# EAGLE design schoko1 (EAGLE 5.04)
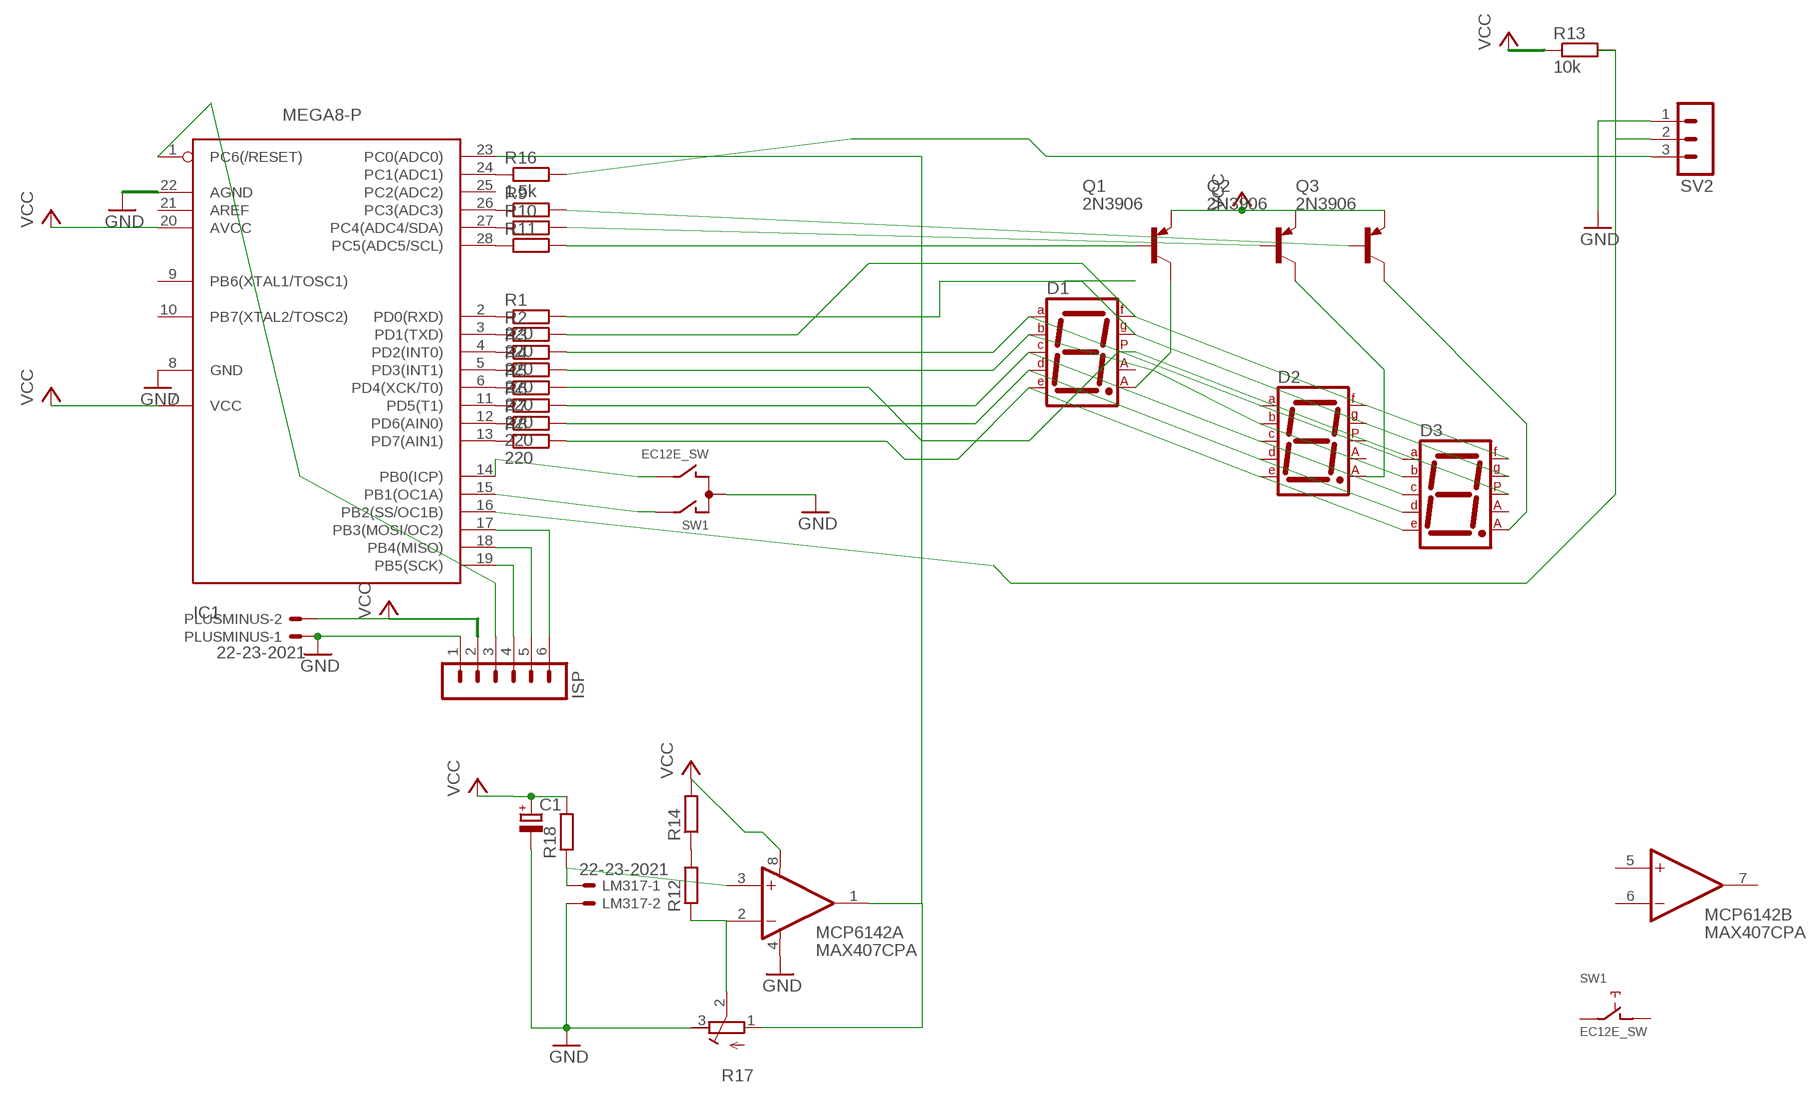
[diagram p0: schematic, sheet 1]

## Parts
C1  CPOL-EUTT2D5L  [TT2D5L]
D1  7SEG-CA  [7SEG-13]
D2  7SEG-CA  [7SEG-13]
D3  7SEG-CA  [7SEG-13]
IC1  MEGA8-P  [DIL28-3]
ISP  MA06-1  [MA06-1]
LM317  22-23-2021  [22-23-2021]
MCP6142  MAX407CPA  [DIL08]
PLUSMINUS  22-23-2021  [22-23-2021]
Q1  2N3906  [TO92]
Q2  2N3906  [TO92]
Q3  2N3906  [TO92]
R1  220  R-EU_0204/7  [0204/7]
R2  220  R-EU_0204/7  [0204/7]
R3  220  R-EU_0204/7  [0204/7]
R4  220  R-EU_0204/7  [0204/7]
R5  220  R-EU_0204/7  [0204/7]
R6  220  R-EU_0204/7  [0204/7]
R7  220  R-EU_0204/7  [0204/7]
R8  220  R-EU_0204/7  [0204/7]
R9  R-EU_0204/7  [0204/7]
R10  R-EU_0204/7  [0204/7]
R11  R-EU_0204/7  [0204/7]
R12  R-EU_0204/7  [0204/7]
R13  10k  R-EU_0204/7  [0204/7]
R14  R-EU_0204/7  [0204/7]
R16  1.5k  R-EU_0204/7  [0204/7]
R17  R-TRIMM64P  [RTRIM64P]
R18  R-EU_0204/7  [0204/7]
SV2  MA03-1  [MA03-1]
SW1  EC12E_SW  [ALPS_EC12E_SW]

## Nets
GND: C1.- IC1.8(GND) IC1.22(AGND) ISP.1 LM317.2 MCP6142.4(A:V-) PLUSMINUS.1 R17.3(A) SV2.1 SW1.C
N$1: D1.7(A) D2.7(A) D3.7(A) R3.2
N$2: D1.6(B) D2.6(B) D3.6(B) R4.2
N$3: D1.4(C) D2.4(C) D3.4(C) R6.2
N$4: D1.2(D) D2.2(D) D3.2(D) R7.2
N$5: D1.1(E) D2.1(E) D3.1(E) R8.2
N$6: D1.9(F) D2.9(F) D3.9(F) R2.2
N$7: D1.8(CA2) Q1.1(C)
N$8: IC1.4(PD2(INT0)) R3.1
N$9: IC1.5(PD3(INT1)) R4.1
N$10: IC1.6(PD4(XCK/T0)) R5.1
N$11: IC1.11(PD5(T1)) R6.1
N$12: IC1.12(PD6(AIN0)) R7.1
N$13: IC1.13(PD7(AIN1)) R8.1
N$14: IC1.2(PD0(RXD)) R1.1
N$15: IC1.3(PD1(TXD)) R2.1
N$16: D2.8(CA2) Q2.1(C)
N$17: D1.5(DP) D2.5(DP) D3.5(DP) R5.2
N$18: D1.10(G) D2.10(G) D3.10(G) R1.2
N$20: D3.8(CA2) Q3.1(C)
N$21: IC1.28(PC5(ADC5/SCL)) R11.1
N$22: IC1.27(PC4(ADC4/SDA)) R10.1
N$23: IC1.26(PC3(ADC3)) R9.1
N$24: Q3.2(B) R9.2
N$25: Q2.2(B) R10.2
N$26: Q1.2(B) R11.2
N$27: IC1.16(PB2(SS/OC1B)) R13.2 SV2.2
N$28: IC1.1(PC6(/RESET)) ISP.3
N$29: IC1.19(PB5(SCK)) ISP.4
N$30: IC1.18(PB4(MISO)) ISP.5
N$31: IC1.17(PB3(MOSI/OC2)) ISP.6
N$33: IC1.14(PB0(ICP)) SW1.B
N$34: IC1.15(PB1(OC1A)) SW1.A
N$37: IC1.24(PC1(ADC1)) R16.1
N$39: R12.2 R14.1
N$43: R16.2 SV2.3
N$44: IC1.23(PC0(ADC0)) MCP6142.1(A:OUT) R17.1(E)
N$45: MCP6142.2(A:-IN) R12.1 R17.2(S)
N$47: LM317.1 MCP6142.3(A:+IN) R18.1
VCC: C1.+ IC1.7(VCC) IC1.20(AVCC) ISP.2 MCP6142.8(A:V+) PLUSMINUS.2 Q1.3(E) Q2.3(E) Q3.3(E) R13.1 R14.2 R18.2
Unconnected: D1.3(CA1) D2.3(CA1) D3.3(CA1) IC1.9(PB6(XTAL1/TOSC1)) IC1.10(PB7(XTAL2/TOSC2)) IC1.21(AREF) IC1.25(PC2(ADC2)) MCP6142.5(B:+IN) MCP6142.6(B:-IN) MCP6142.7(B:OUT) SW1.D SW1.E SW1.GND1(G) SW1.GND2(G)

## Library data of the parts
C1 = resistor:CPOL-EU: POLARIZED CAPACITOR, European symbol
D1-D3 = special:7SEG-CA: 7-segment DISPLAY single anode, 13 mm
IC1 = atmel:MEGA8-P: MICROCONTROLLER 8 Kbytes FLASH, 1 kbytes SRAM, 512 bytes EEPROM, USART, 4-channel 10 bit ADC, 2-channel 8 bit ADC Pin compatible with Atmega48, ATMega88, ATMega168 Source: avr.lbr
ISP = con-lstb:MA06-1: PIN HEADER
LM317 PLUSMINUS = con-molex:22-23-2021: .100" (2.54mm) Center Header - 2 Pin
MCP6142 = maxim:MAX407CPA: OP AMP
Q1-Q3 = transistor-pnp:2N3906: PNP Transistor
R1-R14 R16 R18 = resistor:R-EU_: RESISTOR, European symbol
R17 = resistor:R-TRIMM: Trimm resistor
SV2 = con-lstb:MA03-1: PIN HEADER
SW1 = switch-alps:EC12E_SW: ALPS rotary Encoder EC12E series with switch

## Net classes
0 default: width 0.508 mm, clearance 0.254 mm
1 220: width 0.762 mm, clearance 0.762 mm

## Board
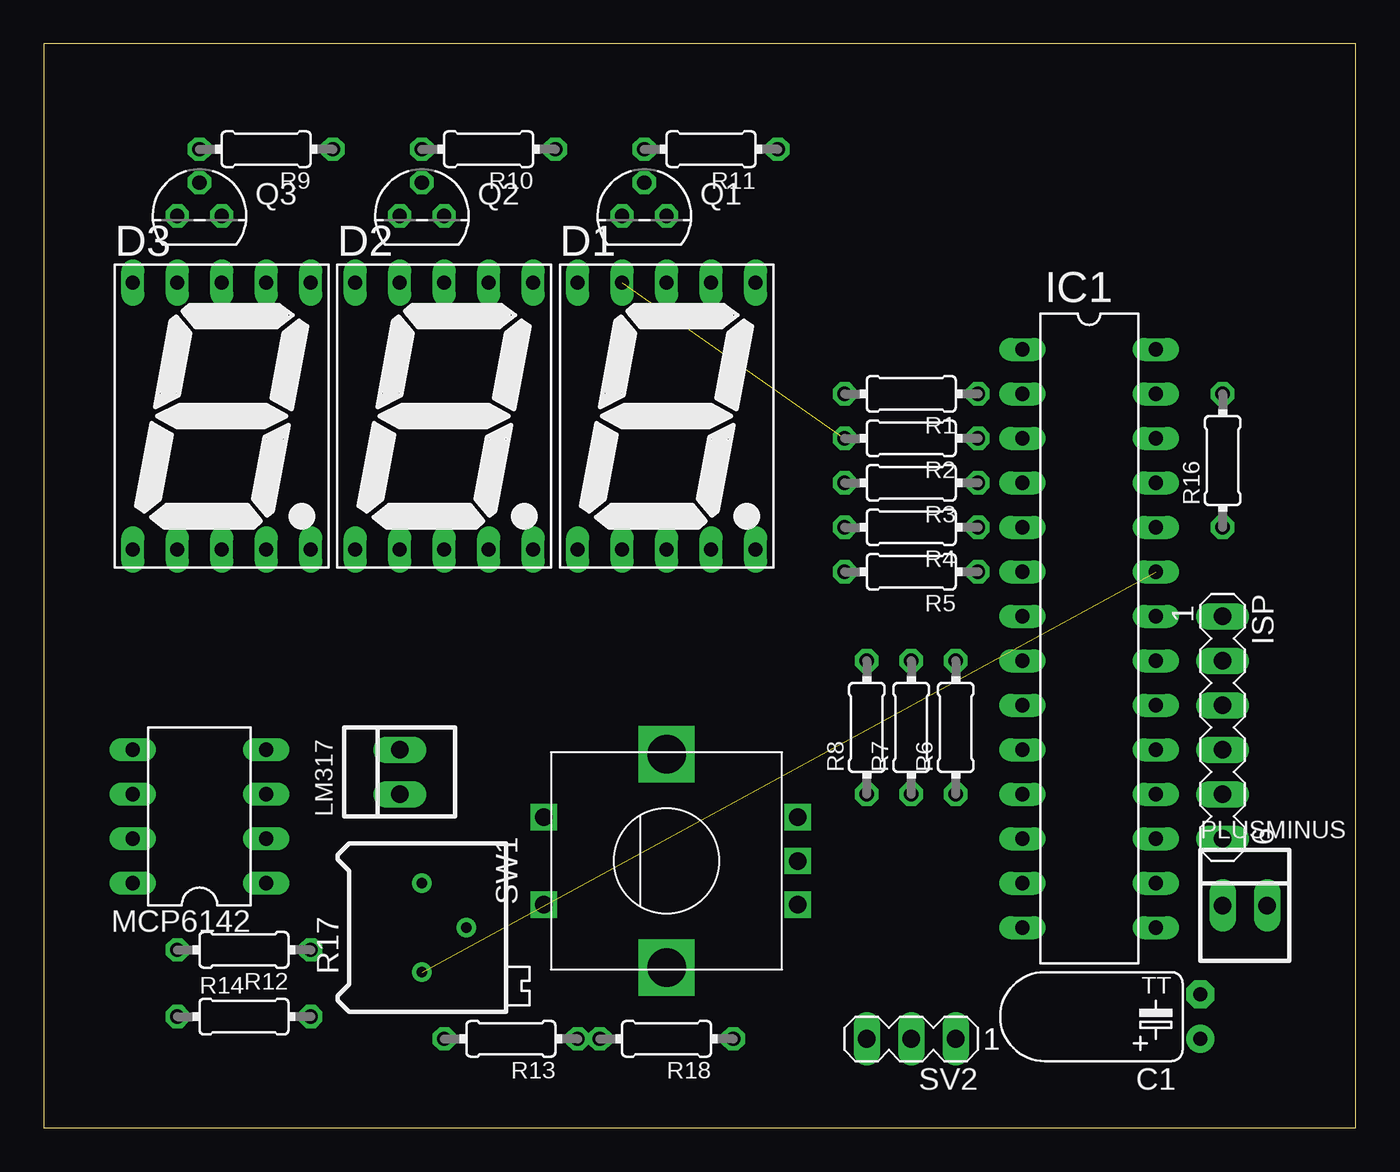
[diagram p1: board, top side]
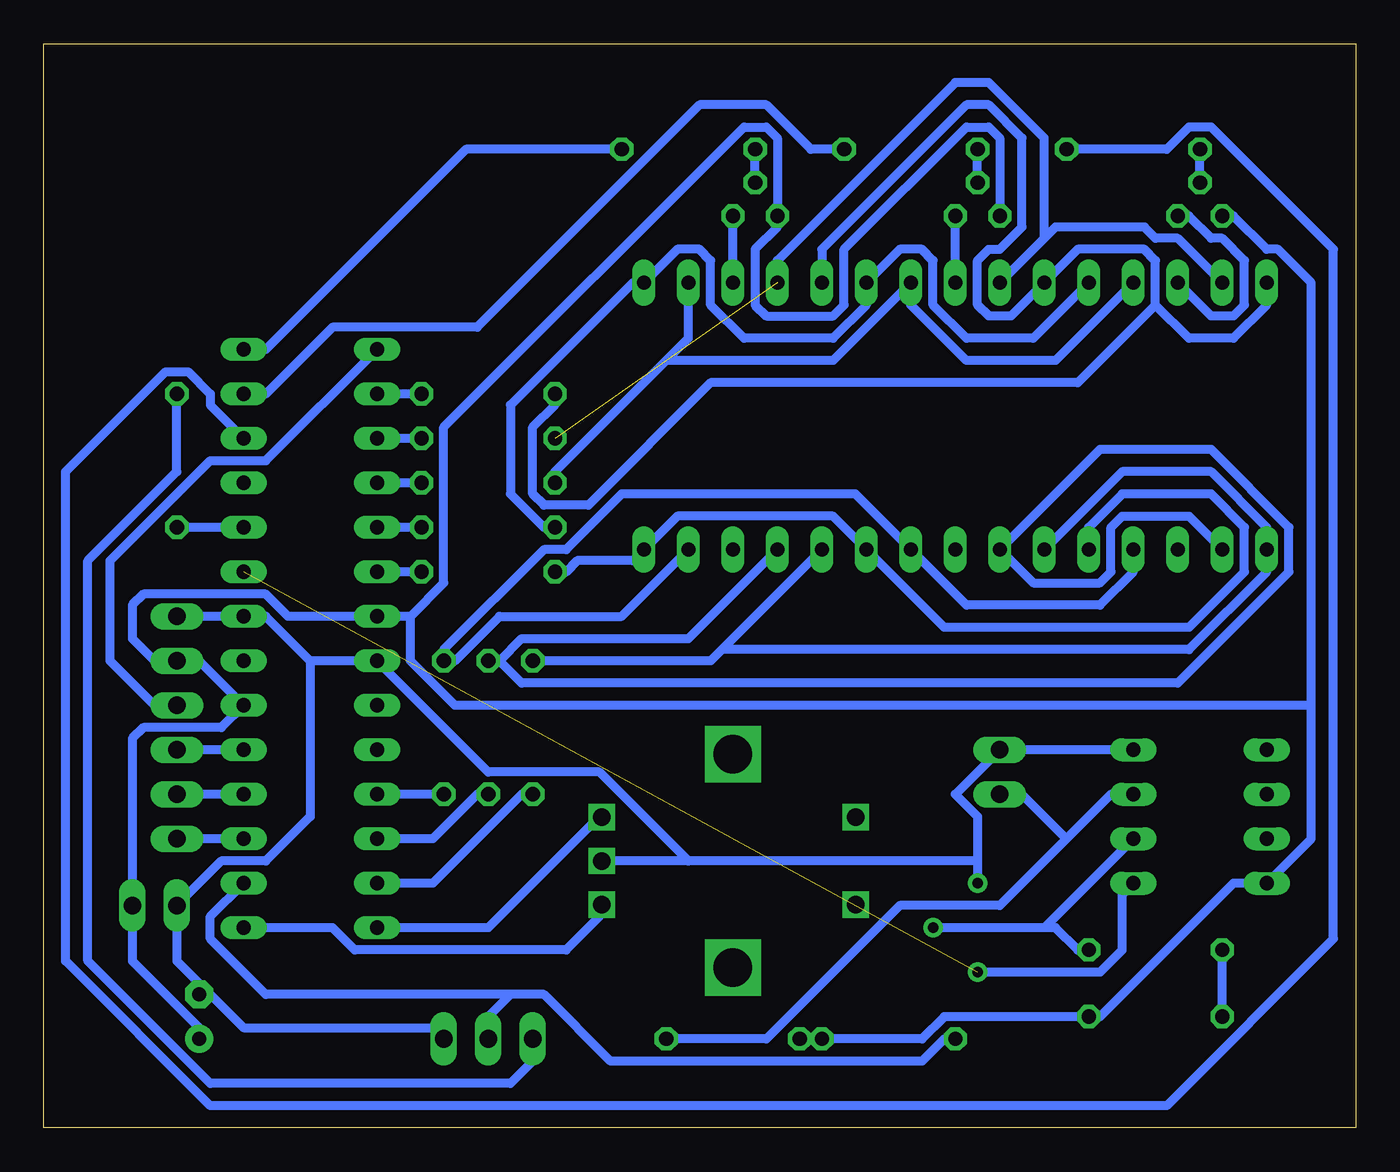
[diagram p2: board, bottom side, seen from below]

Size 74.91 x 61.9 mm. Coordinates in mm from the lower left corner, seen from the top.
Outline: 0,0 74.91,0 74.91,61.9 0,61.9 0,0
Copper layers (1*16): Top 0.035mm / dielectric 1.5mm / Bottom 0.035mm
Design rules "default": minimum track width 10mil, minimum drill 24mil, track to track 8mil, track to pad 8mil, pad to pad 8mil, via to via 8mil, smd to smd 8mil, copper to edge 40mil, drill to drill 8mil, minimum pad ring 10mil, minimum via ring 8mil, stop-mask expansion 4mil, vias tented up to drill 0mil, thermal gap 10mil

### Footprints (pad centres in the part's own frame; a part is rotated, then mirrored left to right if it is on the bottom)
TT2D5L = drill 0.813 pad 1.6 round: + -1.27,0 | drill 0.813 pad 1.6 octagon: - 1.27,0
7SEG-13 = drill 0.813 long: 1 -5.08,-7.62; 2 -2.54,-7.62; 3 0,-7.62; 4 2.54,-7.62; 5 5.08,-7.62; 6 5.08,7.62; 7 2.54,7.62; 8 0,7.62; 9 -2.54,7.62; 10 -5.08,7.62
DIL28-3 = drill 0.813 long: 1 -16.51,-3.81; 2 -13.97,-3.81; 3 -11.43,-3.81; 4 -8.89,-3.81; 5 -6.35,-3.81; 6 -3.81,-3.81; 7 -1.27,-3.81; 8 1.27,-3.81; 9 3.81,-3.81; 10 6.35,-3.81; 11 8.89,-3.81; 12 11.43,-3.81; 13 13.97,-3.81; 14 16.51,-3.81; 15 16.51,3.81; 16 13.97,3.81; 17 11.43,3.81; 18 8.89,3.81; 19 6.35,3.81; 20 3.81,3.81; 21 1.27,3.81; 22 -1.27,3.81; 23 -3.81,3.81; 24 -6.35,3.81; 25 -8.89,3.81; 26 -11.43,3.81; 27 -13.97,3.81; 28 -16.51,3.81
MA06-1 = drill 1.016 long: 1 -6.35,0; 2 -3.81,0; 3 -1.27,0; 4 1.27,0; 5 3.81,0; 6 6.35,0
22-23-2021 = drill 1 long: 1 -1.27,0; 2 1.27,0
DIL08 = drill 0.813 long: 1 -3.81,-3.81; 2 -1.27,-3.81; 3 1.27,-3.81; 4 3.81,-3.81; 5 3.81,3.81; 6 1.27,3.81; 7 -1.27,3.81; 8 -3.81,3.81
TO92 = drill 0.813 octagon: 1 1.27,0; 2 0,1.905; 3 -1.27,0
0204/7 = drill 0.813 octagon: 1 -3.81,0; 2 3.81,0
RTRIM64P = drill 0.61 round: 1 0,-2.54; 2 2.54,0; 3 0,2.54
MA03-1 = drill 1.016 long: 1 -2.54,0; 2 0,0; 3 2.54,0
ALPS_EC12E_SW = drill 1 square: A -2.5,-7.5; B 2.5,-7.5; C 0,-7.5; D -2.5,7; E 2.5,7 | drill 2.2 square: GND1 -6.1,0; GND2 6.1,0

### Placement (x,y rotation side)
C1  66.04,6.35 90 top
D1  35.56,40.64 0 top
D2  22.86,40.64 0 top
D3  10.16,40.64 0 top
IC1  59.69,27.94 270 top
ISP  67.31,22.86 270 top
LM317  20.32,20.32 90 top
MCP6142  8.89,17.78 90 top
PLUSMINUS  68.58,12.7 0 top
Q1  34.29,52.07 0 top
Q2  21.59,52.07 0 top
Q3  8.89,52.07 0 top
R1  49.53,41.91 180 top
R2  49.53,39.37 180 top
R3  49.53,36.83 180 top
R4  49.53,34.29 180 top
R5  49.53,31.75 180 top
R6  52.07,22.86 90 top
R7  49.53,22.86 90 top
R8  46.99,22.86 90 top
R9  12.7,55.88 180 top
R10  25.4,55.88 180 top
R11  38.1,55.88 180 top
R12  11.43,10.16 180 top
R13  26.67,5.08 180 top
R14  11.43,6.35 0 top
R16  67.31,38.1 90 top
R17  21.59,11.43 0 top
R18  35.56,5.08 180 top
SV2  49.53,5.08 180 top
SW1  35.56,15.24 90 top

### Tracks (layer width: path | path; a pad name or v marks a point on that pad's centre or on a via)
GND
  Bottom 0.508: SV2.1 52.7,5.71 63.5,5.71 65.41,7.62 C1.- 66.04,8.25 67.31,9.52 PLUSMINUS.1 64.77,15.24 62.23,15.24 59.69,17.78 59.69,26.67 | 59.69,26.67 62.23,29.21 IC1.22 ISP.1 | 59.69,26.67 IC1.8 49.53,20.32 43.18,20.32 38.1,15.24 | 21.59,15.24 21.59,17.78 22.86,19.05 LM317.2 MCP6142.4 | 21.59,15.24 R17.3 | 21.59,15.24 38.1,15.24 | 38.1,15.24 SW1.C
N$1
  Bottom 0.508: D3.7 17.14,43.82 22.23,43.82 25.4,46.99 D2.7 29.84,43.82 39.37,43.82 | 39.37,43.82 38.1,45.09 D1.7 | 39.37,43.82 45.72,37.46 R3.2
N$2
  Bottom 0.508: D3.6 18.41,45.09 22.23,45.09 24.13,46.99 24.13,49.53 24.77,50.16 26.04,50.16 D2.6 27.94,46.99 29.84,45.09 34.92,45.09 36.83,46.99 36.83,49.53 37.47,50.16 38.73,50.16 D1.6 41.27,48.26 48.26,41.27 48.26,36.2 46.35,34.29 R4.2
N$3
  Bottom 0.508: D3.4 12.7,31.75 14.61,29.84 22.23,29.84 D2.4 28.57,36.2 41.91,36.2 45.09,33.02 46.35,33.02 52.07,27.3 R6.2 51.44,26.67 48.9,29.21 41.91,29.21 D1.4
N$4
  Bottom 0.508: D3.2 9.53,34.93 13.34,34.93 13.97,34.29 13.97,31.75 14.61,31.12 18.41,31.12 D2.2 14.61,38.73 8.26,38.73 3.81,34.29 3.81,31.75 10.16,25.4 47.62,25.4 48.9,26.67 | 48.9,26.67 47.62,27.94 38.1,27.94 D1.2 | 48.9,26.67 R7.2
N$5
  Bottom 0.508: D2.1 13.34,37.46 8.26,37.46 5.08,34.29 D3.1 5.08,31.75 9.53,27.3 36.2,27.3 | 36.2,27.3 36.83,26.67 R8.2 | 36.2,27.3 D1.1
N$6  (1 unrouted)
  Bottom 0.508: 17.78,50.8 17.14,51.43 12.06,51.43 11.43,50.8 10.16,50.8 D3.9 | 17.78,50.8 D2.9 | 17.78,50.8 17.78,56.51 20.95,59.69 22.86,59.69 33.02,49.53 D1.9
N$7
  Bottom 0.508: D1.8 Q1.1
N$8
  Bottom 0.508: R3.1 IC1.4
N$9
  Bottom 0.508: R4.1 IC1.5
N$10
  Bottom 0.508: R5.1 IC1.6
N$11
  Bottom 0.508: R6.1 IC1.11
N$12
  Bottom 0.508: R7.1 50.16,19.05 52.7,16.51 IC1.12
N$13
  Bottom 0.508: R8.1 47.62,19.05 52.7,13.97 IC1.13
N$14
  Bottom 0.508: R1.1 IC1.2
N$15
  Bottom 0.508: R2.1 IC1.3
N$16
  Bottom 0.508: D2.8 Q2.1
N$17
  Bottom 0.508: R5.2 45.09,31.75 44.45,32.38 41.27,32.38 D1.5 38.73,34.93 29.84,34.93 D2.5 23.5,28.57 9.53,28.57 6.35,31.75 6.35,34.29 8.26,36.2 13.34,36.2 15.24,34.29 D3.5
N$18
  Bottom 0.508: 11.43,46.99 9.53,45.09 6.99,45.09 5.08,46.99 D3.10 | 11.43,46.99 11.43,49.53 12.06,50.16 15.88,50.16 D2.10 19.68,46.35 20.95,46.35 21.59,46.99 21.59,49.53 20.95,50.16 20.32,50.16 19.05,51.43 19.05,56.51 20.95,58.42 22.23,58.42 30.48,50.16 D1.10 | 11.43,46.99 15.88,42.54 36.83,42.54 43.81,35.56 46.35,35.56 46.99,36.2 46.99,40.01 45.72,41.27 R1.2
N$20
  Bottom 0.508: D3.8 8.26,46.35 6.99,46.35 6.35,46.99 6.35,49.53 7.62,50.8 8.26,50.8 9.53,52.07 Q3.1
N$21
  Bottom 0.508: R11.1 50.8,55.88 62.23,44.45 IC1.28
N$22
  Bottom 0.508: R10.1 31.11,55.88 33.66,58.42 37.47,58.42 50.16,45.72 58.42,45.72 62.23,41.91 IC1.27
N$23
  Bottom 0.508: R9.1 10.79,55.88 9.53,57.15 8.26,57.15 1.27,50.16 1.27,10.8 10.79,1.27 65.41,1.27 73.66,9.52 73.66,37.46 67.94,43.18 66.67,43.18 65.41,41.91 65.41,41.27 IC1.26
N$24
  Bottom 0.508: Q3.2 R9.2
N$25
  Bottom 0.508: Q2.2 R10.2
N$26
  Bottom 0.508: Q1.2 R11.2
N$27
  Bottom 0.508: 48.26,7.62 46.35,7.62 42.55,3.81 24.77,3.81 23.5,5.08 R13.2 | 48.26,7.62 49.53,6.35 SV2.2 | 48.26,7.62 62.23,7.62 65.41,10.8 65.41,12.06 IC1.16
N$28
  Bottom 0.508: IC1.1 62.23,38.1 65.41,38.1 71.12,32.38 71.12,26.67 68.58,24.13 ISP.3
N$29
  Bottom 0.508: IC1.19 ISP.4
N$30
  Bottom 0.508: IC1.18 ISP.5
N$31
  Bottom 0.508: IC1.17 ISP.6
N$33
  Bottom 0.508: IC1.14 49.53,11.43 43.18,17.78 SW1.B
N$34
  Bottom 0.508: IC1.15 58.42,11.43 57.15,10.16 45.09,10.16 43.18,12.06 SW1.A
N$37
  Bottom 0.508: IC1.24 R16.1
N$39
  Bottom 0.508: R14.1 R12.2
N$43
  Bottom 0.508: R16.2 67.31,37.46 72.39,32.38 72.39,9.52 65.41,2.54 48.26,2.54 46.99,3.81 SV2.3
N$44  (1 unrouted)
  Bottom 0.508: R17.1 14.61,8.89 13.34,10.16 13.34,13.34 MCP6142.1
N$45
  Bottom 0.508: 17.78,11.43 17.14,11.43 15.88,10.16 R12.1 | 17.78,11.43 R17.2 | 17.78,11.43 MCP6142.2
N$47
  Bottom 0.508: 16.51,16.51 13.97,19.05 MCP6142.3 | 16.51,16.51 20.32,12.7 26.04,12.7 33.66,5.08 R18.1 | 16.51,16.51 19.05,19.05 LM317.1
VCC
  Bottom 0.508: R18.2 R13.1 24.77,5.08 23.5,6.35 R14.2 14.61,6.35 6.99,13.97 MCP6142.8 2.54,16.51 2.54,24.13 | 2.54,24.13 2.54,48.26 4.45,50.16 5.08,50.16 6.99,52.07 Q3.3 | Q2.3 20.32,56.51 20.95,57.15 22.23,57.15 29.21,50.16 29.21,46.99 29.84,46.35 33.66,46.35 34.29,46.99 34.29,50.16 33.02,51.43 Q1.3 33.02,56.51 33.66,57.15 34.92,57.15 52.07,40.01 52.07,31.12 53.98,29.21 | C1.+ 66.04,5.71 69.85,9.52 PLUSMINUS.2 69.85,22.23 69.22,22.86 64.77,22.86 IC1.20 66.04,26.67 ISP.2 68.58,26.67 69.85,27.94 69.85,29.84 69.22,30.48 62.23,30.48 60.96,29.21 IC1.7 53.98,29.21 | 2.54,24.13 51.44,24.13 53.98,26.67 53.98,29.21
